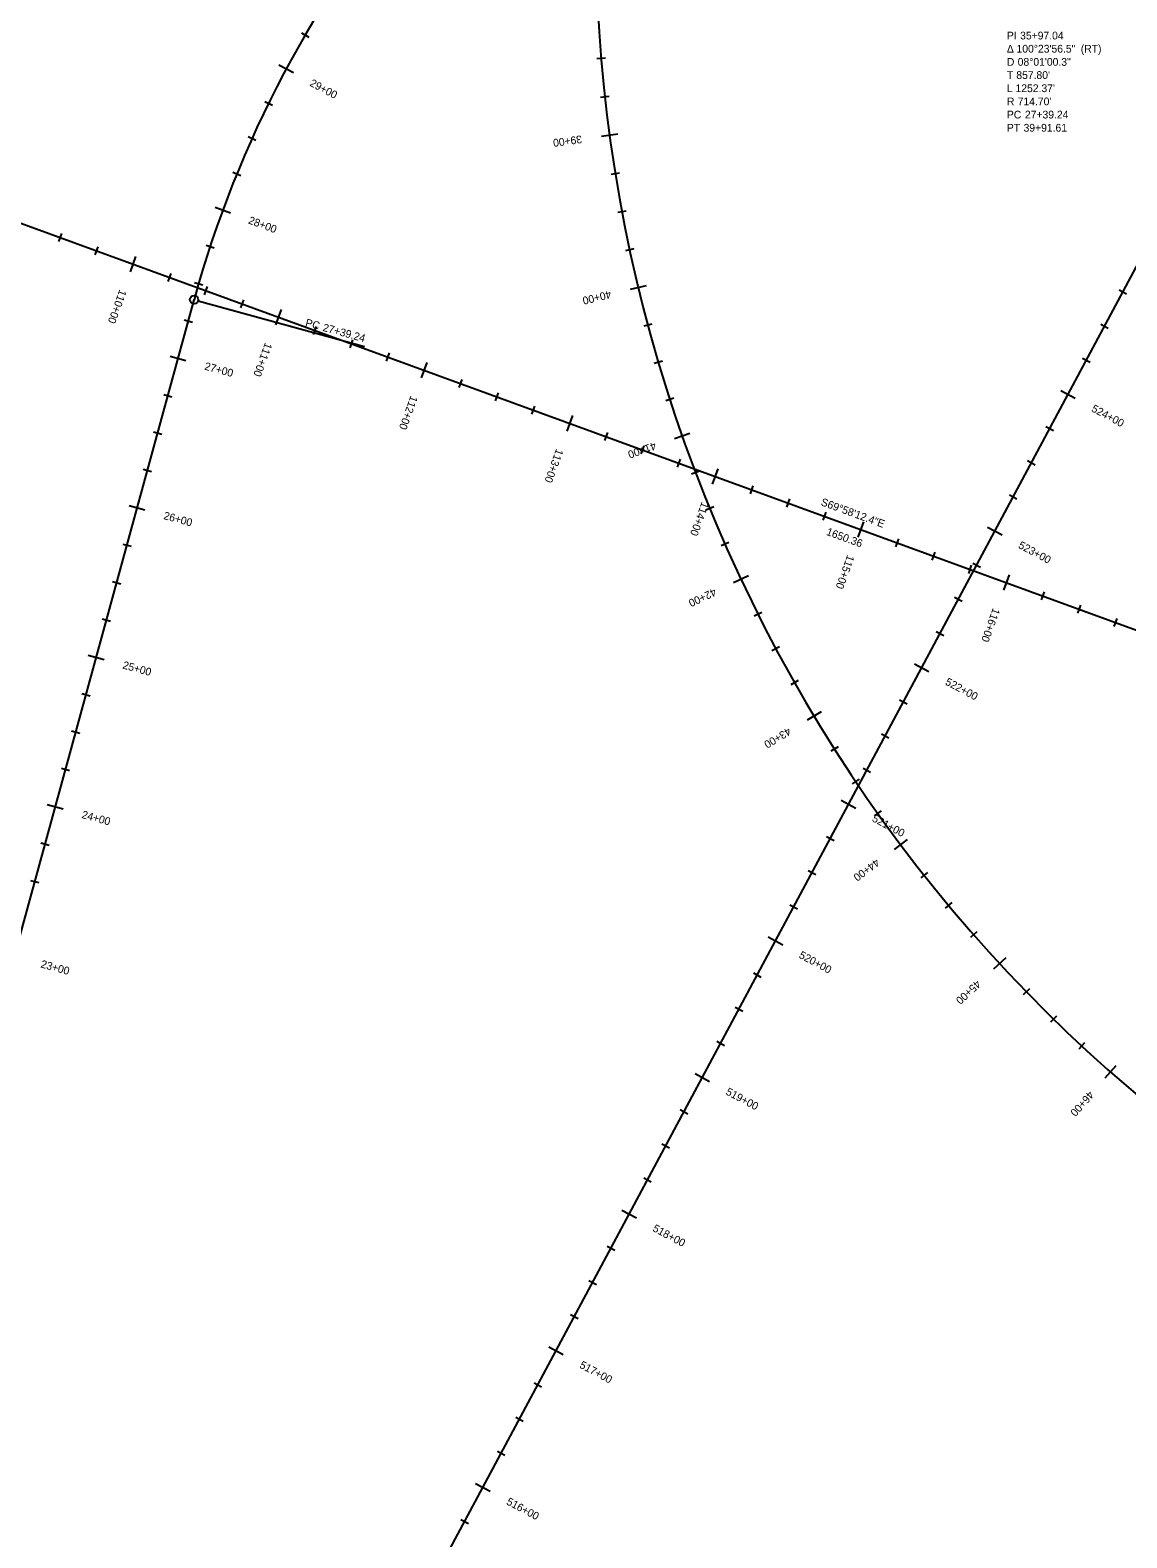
# Model space of a CAD drawing. Extents: x 2300830 to 2307917, y 756066 to 766359.
# Drawn here: x 2302821 to 2303529, y 760655 to 761628 of the extents above; entities that cross this region are included whole.
import ezdxf

# ---------------------------------------------------------------- set-up
doc = ezdxf.new("R2010")
doc.units = 0
for name, color, linetype in [('Default', 7, 'Continuous'), ('Draft_Bearing Label', 7, 'Continuous'), ('Draft_Curve Data Label', 7, 'Continuous'), ('Draft_Station Cardinal Lines', 7, 'Continuous'), ('Draft_Station Cardinal Points', 7, 'Continuous'), ('Draft_Station Labels Major', 7, 'Continuous'), ('Draft_Station Ticks Major', 7, 'Continuous'), ('Draft_Station Ticks Minor', 7, 'Continuous'), ('Geom_Baseline', 7, 'Continuous')]:
    doc.layers.add(name, color=color, linetype=linetype)

msp = doc.modelspace()

# ---------------------------------------------------------------- linework, layer by layer
at = {"layer": 'Default'}
for p, q in [((2301469.01, 757616.61), (2303797.09, 761964.97)), ((2301469.01, 757616.61), (2303797.09, 761964.97)), ((2302574.77, 761591.29), (2304125.31, 761026.02)), ((2302467.58, 759777.24), (2302927, 761454.36))]:
    msp.add_line(p, q, dxfattribs=at)
for centre, radius, start, end in [((2304169.7, 761693.02), 983.53, 137.61666, 272.52241), ((2303616.31, 761265.54), 714.7, 64.28167, 164.6807)]:
    msp.add_arc(centre, radius, start, end, dxfattribs=at)
at = {"layer": 'Draft_Station Cardinal Lines'}
msp.add_line((2302929.57, 761453.65), (2303036.95, 761424.24), dxfattribs=at)
at = {"layer": 'Draft_Station Cardinal Points'}
for p, q in [((2302927, 761454.36), (2302927, 761454.36)), ((2303036.95, 761424.24), (2303036.95, 761424.24))]:
    msp.add_line(p, q, dxfattribs=at)
msp.add_circle((2302927, 761454.36), 2.67, dxfattribs=at)
at = {"layer": 'Draft_Station Ticks Major'}
for p, q in [((2302981.77, 761605.87), (2302991.13, 761600.85)), ((2303200.44, 761561.1), (2303189.92, 761559.67)), ((2302940.51, 761514.05), (2302950.48, 761510.38)), ((2302889.27, 761482.32), (2302885.63, 761472.34)), ((2303218.84, 761463.4), (2303208.51, 761460.91)), ((2302983.22, 761448.07), (2302979.58, 761438.09)), ((2302911.48, 761417.92), (2302921.72, 761415.11)), ((2303077.17, 761413.82), (2303073.53, 761403.84)), ((2303486.31, 761395.8), (2303495.67, 761390.78)), ((2303171.12, 761379.57), (2303167.49, 761369.59)), ((2303247.05, 761368.08), (2303237.03, 761364.55)), ((2303265.08, 761345.32), (2303261.44, 761335.34)), ((2302885.06, 761321.47), (2302895.3, 761318.67)), ((2303359.03, 761311.07), (2303355.39, 761301.09)), ((2303439.1, 761307.64), (2303448.47, 761302.62)), ((2303284.8, 761276.11), (2303275.19, 761271.58)), ((2303452.98, 761276.81), (2303449.34, 761266.84)), ((2302858.64, 761225.03), (2302868.88, 761222.22)), ((2303391.9, 761219.48), (2303401.27, 761214.46)), ((2303331.68, 761188.44), (2303322.59, 761182.96)), ((2302832.22, 761128.58), (2302842.46, 761125.77)), ((2303344.7, 761131.32), (2303354.07, 761126.3)), ((2303387.23, 761105.99), (2303378.73, 761099.62)), ((2303297.5, 761043.16), (2303306.87, 761038.14)), ((2303450.85, 761029.6), (2303443.05, 761022.4)), ((2303521.9, 760960.07), (2303514.87, 760952.11)), ((2303250.3, 760955), (2303259.67, 760949.98)), ((2303203.1, 760866.84), (2303212.47, 760861.82)), ((2303155.9, 760778.68), (2303165.27, 760773.66)), ((2303108.7, 760690.52), (2303118.07, 760685.5))]:
    msp.add_line(p, q, dxfattribs=at)
at = {"layer": 'Draft_Station Ticks Minor'}
for p, q in [((2302996.29, 761626.55), (2303001.06, 761623.77)), ((2303192.42, 761610.3), (2303186.92, 761609.84)), ((2302972.57, 761582.33), (2302977.52, 761579.89)), ((2303194.84, 761585.49), (2303189.35, 761584.89)), ((2302961.89, 761559.62), (2302966.92, 761557.36)), ((2302952, 761536.55), (2302957.11, 761534.47)), ((2303201.56, 761536.09), (2303196.11, 761535.21)), ((2303205.86, 761511.54), (2303200.44, 761510.52)), ((2302841.41, 761497.02), (2302839.52, 761491.84)), ((2302864.9, 761488.46), (2302863.01, 761483.27)), ((2302934.68, 761489.46), (2302939.93, 761487.73)), ((2303210.78, 761487.1), (2303205.39, 761485.94)), ((2302911.87, 761471.33), (2302909.98, 761466.15)), ((2302927.27, 761465.48), (2302932.57, 761463.94)), ((2302935.36, 761462.77), (2302933.47, 761457.59)), ((2302958.85, 761454.21), (2302956.96, 761449.02)), ((2303523.98, 761460.7), (2303528.85, 761458.09)), ((2302920.57, 761441.35), (2302925.9, 761439.89)), ((2303005.82, 761437.08), (2303003.93, 761431.9)), ((2303222.49, 761438.64), (2303217.16, 761437.21)), ((2303512.18, 761438.66), (2303517.05, 761436.05)), ((2303029.31, 761428.52), (2303027.42, 761423.33)), ((2303052.8, 761419.96), (2303050.91, 761414.77)), ((2303229.26, 761414.65), (2303223.96, 761413.08)), ((2303500.38, 761416.62), (2303505.25, 761414.01)), ((2303099.78, 761402.83), (2303097.89, 761397.65)), ((2302907.36, 761393.13), (2302912.69, 761391.67)), ((2303123.26, 761394.27), (2303121.37, 761389.08)), ((2303146.75, 761385.71), (2303144.86, 761380.52)), ((2303236.64, 761390.84), (2303231.39, 761389.13)), ((2302900.76, 761369.02), (2302906.08, 761367.56)), ((2303193.73, 761368.58), (2303191.84, 761363.4)), ((2303476.78, 761372.54), (2303481.65, 761369.93)), ((2303217.22, 761360.02), (2303215.33, 761354.83)), ((2303240.7, 761351.46), (2303238.81, 761346.27)), ((2303464.98, 761350.5), (2303469.85, 761347.89)), ((2302894.15, 761344.9), (2302899.48, 761343.45)), ((2303253.2, 761343.81), (2303248.04, 761341.85)), ((2303287.68, 761334.33), (2303285.79, 761329.14)), ((2303453.18, 761328.46), (2303458.05, 761325.85)), ((2303262.37, 761320.63), (2303257.26, 761318.54)), ((2303311.17, 761325.77), (2303309.28, 761320.58)), ((2303334.65, 761317.2), (2303332.76, 761312.02)), ((2303381.63, 761300.08), (2303379.74, 761294.89)), ((2302880.94, 761296.68), (2302886.27, 761295.22)), ((2303272.13, 761297.69), (2303267.07, 761295.47)), ((2303405.12, 761291.52), (2303403.23, 761286.33)), ((2303428.61, 761282.95), (2303426.72, 761277.77)), ((2303429.58, 761284.38), (2303434.45, 761281.77)), ((2302874.34, 761272.57), (2302879.66, 761271.11)), ((2303417.78, 761262.34), (2303422.65, 761259.73)), ((2303475.58, 761265.83), (2303473.69, 761260.64)), ((2303293.37, 761252.59), (2303288.44, 761250.11)), ((2303499.07, 761257.27), (2303497.18, 761252.08)), ((2302867.73, 761248.46), (2302873.06, 761247)), ((2303405.98, 761240.3), (2303410.85, 761237.69)), ((2303522.56, 761248.7), (2303520.67, 761243.52)), ((2303304.85, 761230.46), (2303299.98, 761227.86)), ((2303316.89, 761208.63), (2303312.09, 761205.9)), ((2302854.52, 761200.23), (2302859.85, 761198.78)), ((2303382.38, 761196.22), (2303387.25, 761193.61)), ((2302847.92, 761176.12), (2302853.24, 761174.66)), ((2303370.58, 761174.18), (2303375.45, 761171.57)), ((2303342.6, 761165.92), (2303337.95, 761162.95)), ((2302841.31, 761152.01), (2302846.64, 761150.55)), ((2303358.78, 761152.14), (2303363.65, 761149.53)), ((2303356.27, 761145.07), (2303351.69, 761141.99)), ((2303370.46, 761124.57), (2303365.96, 761121.37)), ((2302828.1, 761103.79), (2302833.43, 761102.33)), ((2303335.18, 761108.06), (2303340.05, 761105.45)), ((2303323.38, 761086.02), (2303328.25, 761083.41)), ((2303400.38, 761084.69), (2303396.05, 761081.27)), ((2302821.5, 761079.67), (2302826.82, 761078.22)), ((2303416.08, 761065.34), (2303411.84, 761061.8)), ((2303311.58, 761063.98), (2303316.45, 761061.37)), ((2303432.28, 761046.39), (2303428.13, 761042.75)), ((2303287.98, 761019.9), (2303292.85, 761017.29)), ((2303466.09, 761009.75), (2303462.13, 761005.9)), ((2303276.18, 760997.86), (2303281.05, 760995.25)), ((2303483.69, 760992.09), (2303479.83, 760988.14)), ((2303264.38, 760975.82), (2303269.25, 760973.21)), ((2303501.72, 760974.88), (2303497.96, 760970.84)), ((2303240.78, 760931.74), (2303245.65, 760929.13)), ((2303228.98, 760909.7), (2303233.85, 760907.09)), ((2303217.18, 760887.66), (2303222.05, 760885.05)), ((2303193.58, 760843.58), (2303198.45, 760840.97)), ((2303181.78, 760821.54), (2303186.65, 760818.93)), ((2303169.98, 760799.5), (2303174.84, 760796.89)), ((2303146.38, 760755.42), (2303151.24, 760752.81)), ((2303134.58, 760733.38), (2303139.44, 760730.77)), ((2303122.78, 760711.34), (2303127.64, 760708.73)), ((2303099.18, 760667.26), (2303104.04, 760664.65))]:
    msp.add_line(p, q, dxfattribs=at)
at = {"layer": 'Geom_Baseline'}
for p, q in [((2301469.01, 757616.61), (2303797.09, 761964.97)), ((2302574.77, 761591.29), (2304125.31, 761026.02)), ((2302467.58, 759777.24), (2302927, 761454.36))]:
    msp.add_line(p, q, dxfattribs=at)
for centre, radius, start, end in [((2304169.7, 761693.02), 983.53, 137.61666, 272.52241), ((2303616.31, 761265.54), 714.7, 64.28167, 164.6807)]:
    msp.add_arc(centre, radius, start, end, dxfattribs=at)

# ---------------------------------------------------------------- texts
at = {"layer": 'Draft_Bearing Label'}
for s, p in [('S69°58\'12.4"E', (2303331.07, 761321.83)), ('1650.36', (2303334.61, 761302.7))]:
    msp.add_text(s, height=5, rotation=339.97011, dxfattribs=at).set_placement(p)
at = {"layer": 'Draft_Curve Data Label'}
for s, p in [('Δ ', (2303451.59, 761613.79)), ('PI ', (2303451.59, 761622.29)), ('100°23\'56.5"', (2303457.81, 761613.79)), ('35+97.04', (2303460.13, 761622.29)), (' (RT)', (2303497.42, 761613.79)), ('D ', (2303451.59, 761605.29)), ('08°01\'00.3"', (2303458.57, 761605.29)), ('T ', (2303451.59, 761596.79)), ("857.80'", (2303457.67, 761596.79)), ('L ', (2303451.59, 761588.29)), ("1252.37'", (2303457.15, 761588.29)), ('R ', (2303451.59, 761579.79)), ("714.70'", (2303458.57, 761579.79)), ('PC ', (2303451.59, 761571.29)), ('27+39.24', (2303463.23, 761571.29)), ('PT ', (2303451.59, 761562.79)), ('39+91.61', (2303462.33, 761562.79))]:
    msp.add_text(s, height=5, dxfattribs=at).set_placement(p)
at = {"layer": 'Draft_Station Cardinal Points'}
for s, p in [('PC', (2302998.42, 761437.37)), ('27+39.24', (2303009.65, 761434.29))]:
    msp.add_text(s, height=5, rotation=344.6807, dxfattribs=at).set_placement(p)
at = {"layer": 'Draft_Station Labels Major'}
for s, rotation, p in [('29+00', 331.79325, (2303001.16, 761592.63)), ('39+00', 187.75064, (2303176.98, 761560.43)), ('28+00', 339.80999, (2302961.55, 761503.65)), ('110+00', 249.97011, (2302878.93, 761461.25)), ('40+00', 193.57614, (2303195.56, 761460.35)), ('111+00', 249.97011, (2302972.88, 761427)), ('27+00', 344.6807, (2302933.33, 761409.34)), ('112+00', 249.97011, (2303066.83, 761392.75)), ('524+00', 331.8357, (2303505.7, 761382.58)), ('113+00', 249.97011, (2303160.78, 761358.5)), ('41+00', 199.40164, (2303224.21, 761362.68)), ('26+00', 344.6807, (2302906.91, 761312.9)), ('114+00', 249.97011, (2303254.73, 761324.25)), ('523+00', 331.8357, (2303458.5, 761294.42)), ('115+00', 249.97011, (2303348.68, 761289.99)), ('42+00', 205.22714, (2303262.62, 761268.42)), ('116+00', 249.97011, (2303442.63, 761255.74)), ('25+00', 344.6807, (2302880.49, 761216.45)), ('522+00', 331.8357, (2303411.3, 761206.26)), ('43+00', 211.05264, (2303310.4, 761178.54)), ('24+00', 344.6807, (2302854.07, 761120)), ('521+00', 331.8357, (2303364.1, 761118.1)), ('44+00', 216.87814, (2303367.06, 761093.98)), ('23+00', 344.6807, (2302827.65, 761023.56)), ('520+00', 331.8357, (2303316.9, 761029.94)), ('45+00', 222.70364, (2303432, 761015.61)), ('519+00', 331.8357, (2303269.7, 760941.78)), ('46+00', 228.52914, (2303504.57, 760944.23)), ('518+00', 331.8357, (2303222.5, 760853.62)), ('517+00', 331.8357, (2303175.3, 760765.46)), ('516+00', 331.8357, (2303128.1, 760677.3))]:
    msp.add_text(s, height=5, rotation=rotation, dxfattribs=at).set_placement(p)

doc.saveas('drawing.dxf')
